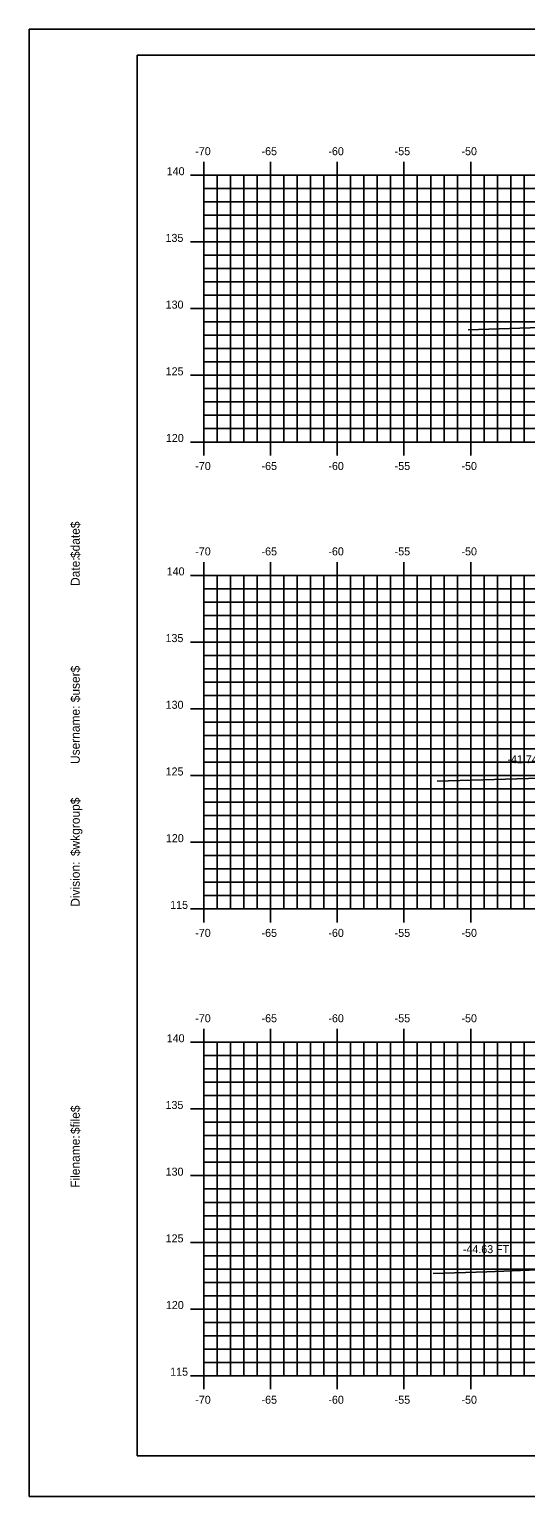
# Model space of a CAD drawing. Extents: x 1146303 to 1146473, y 608981 to 609091.
# Drawn here: x 1146302.8 to 1146340, y 608981.3 to 609091.3 of the extents above; entities that cross this region are included whole.
import ezdxf

# ---------------------------------------------------------------- set-up
doc = ezdxf.new("R2010")
doc.units = 0
for name, color, linetype in [('BORDER', 7, 'Continuous'), ('D_Text_Standard', 7, 'Continuous'), ('H_V ANNOTATION', 7, 'Continuous'), ('MAJOR', 7, 'Continuous'), ('MINOR', 7, 'Continuous'), ('PLOT BOUNDARY', 7, 'Continuous'), ('S_Roadway_Centerline', 7, 'Continuous')]:
    doc.layers.add(name, color=color, linetype=linetype)

msp = doc.modelspace()

# ---------------------------------------------------------------- linework, layer by layer
at = {"layer": 'BORDER'}
msp.add_lwpolyline([(1146310.91, 608984.34), (1146470.91, 608984.34), (1146470.91, 609089.34), (1146310.91, 609089.34)], close=True, dxfattribs=at)
at = {"layer": 'MAJOR'}
for p, q in [((1146315.91, 609081.34), (1146315.91, 609080.34)), ((1146320.91, 609081.34), (1146320.91, 609080.34)), ((1146325.91, 609081.34), (1146325.91, 609080.34)), ((1146330.91, 609081.34), (1146330.91, 609080.34)), ((1146335.91, 609081.34), (1146335.91, 609080.34)), ((1146314.91, 609080.34), (1146315.91, 609080.34)), ((1146315.91, 609080.34), (1146455.91, 609080.34)), ((1146315.91, 609060.34), (1146315.91, 609080.34)), ((1146315.91, 609060.34), (1146315.91, 609080.34)), ((1146315.91, 609080.34), (1146455.91, 609080.34)), ((1146320.91, 609060.34), (1146320.91, 609080.34)), ((1146325.91, 609060.34), (1146325.91, 609080.34)), ((1146330.91, 609060.34), (1146330.91, 609080.34)), ((1146335.91, 609060.34), (1146335.91, 609080.34)), ((1146314.91, 609075.34), (1146315.91, 609075.34)), ((1146315.91, 609075.34), (1146455.91, 609075.34)), ((1146314.91, 609070.34), (1146315.91, 609070.34)), ((1146315.91, 609070.34), (1146455.91, 609070.34)), ((1146314.91, 609065.34), (1146315.91, 609065.34)), ((1146315.91, 609065.34), (1146455.91, 609065.34)), ((1146314.91, 609060.34), (1146315.91, 609060.34)), ((1146315.91, 609060.34), (1146455.91, 609060.34)), ((1146315.91, 609060.34), (1146455.91, 609060.34)), ((1146315.91, 609059.33), (1146315.91, 609060.34)), ((1146320.91, 609059.33), (1146320.91, 609060.34)), ((1146325.91, 609059.33), (1146325.91, 609060.34)), ((1146330.91, 609059.33), (1146330.91, 609060.34)), ((1146335.91, 609059.33), (1146335.91, 609060.34)), ((1146315.91, 609051.34), (1146315.91, 609050.34)), ((1146320.91, 609051.34), (1146320.91, 609050.34)), ((1146325.91, 609051.34), (1146325.91, 609050.34)), ((1146330.91, 609051.34), (1146330.91, 609050.34)), ((1146335.91, 609051.34), (1146335.91, 609050.34)), ((1146314.91, 609050.34), (1146315.91, 609050.34)), ((1146315.91, 609050.34), (1146455.91, 609050.34)), ((1146315.91, 609025.34), (1146315.91, 609050.34)), ((1146315.91, 609025.34), (1146315.91, 609050.34)), ((1146315.91, 609050.34), (1146455.91, 609050.34)), ((1146320.91, 609025.34), (1146320.91, 609050.34)), ((1146325.91, 609025.34), (1146325.91, 609050.34)), ((1146330.91, 609025.34), (1146330.91, 609050.34)), ((1146335.91, 609025.34), (1146335.91, 609050.34)), ((1146314.91, 609045.34), (1146315.91, 609045.34)), ((1146315.91, 609045.34), (1146455.91, 609045.34)), ((1146314.91, 609040.34), (1146315.91, 609040.34)), ((1146315.91, 609040.34), (1146455.91, 609040.34)), ((1146314.91, 609035.34), (1146315.91, 609035.34)), ((1146315.91, 609035.34), (1146455.91, 609035.34)), ((1146314.91, 609030.34), (1146315.91, 609030.34)), ((1146315.91, 609030.34), (1146455.91, 609030.34)), ((1146314.91, 609025.34), (1146315.91, 609025.34)), ((1146315.91, 609025.34), (1146455.91, 609025.34)), ((1146315.91, 609025.34), (1146455.91, 609025.34)), ((1146315.91, 609024.33), (1146315.91, 609025.34)), ((1146320.91, 609024.33), (1146320.91, 609025.34)), ((1146325.91, 609024.33), (1146325.91, 609025.34)), ((1146330.91, 609024.33), (1146330.91, 609025.34)), ((1146335.91, 609024.33), (1146335.91, 609025.34)), ((1146315.91, 609016.34), (1146315.91, 609015.34)), ((1146320.91, 609016.34), (1146320.91, 609015.34)), ((1146325.91, 609016.34), (1146325.91, 609015.34)), ((1146330.91, 609016.34), (1146330.91, 609015.34)), ((1146335.91, 609016.34), (1146335.91, 609015.34)), ((1146314.91, 609015.34), (1146315.91, 609015.34)), ((1146315.91, 609015.34), (1146455.91, 609015.34)), ((1146315.91, 608990.34), (1146315.91, 609015.34)), ((1146315.91, 608990.34), (1146315.91, 609015.34)), ((1146315.91, 609015.34), (1146455.91, 609015.34)), ((1146320.91, 608990.34), (1146320.91, 609015.34)), ((1146325.91, 608990.34), (1146325.91, 609015.34)), ((1146330.91, 608990.34), (1146330.91, 609015.34)), ((1146335.91, 608990.34), (1146335.91, 609015.34)), ((1146314.91, 609010.34), (1146315.91, 609010.34)), ((1146315.91, 609010.34), (1146455.91, 609010.34)), ((1146314.91, 609005.34), (1146315.91, 609005.34)), ((1146315.91, 609005.34), (1146455.91, 609005.34)), ((1146314.91, 609000.34), (1146315.91, 609000.34)), ((1146315.91, 609000.34), (1146455.91, 609000.34)), ((1146314.91, 608995.34), (1146315.91, 608995.34)), ((1146315.91, 608995.34), (1146455.91, 608995.34)), ((1146314.91, 608990.34), (1146315.91, 608990.34)), ((1146315.91, 608990.34), (1146455.91, 608990.34)), ((1146315.91, 608990.34), (1146455.91, 608990.34)), ((1146315.91, 608989.33), (1146315.91, 608990.34)), ((1146320.91, 608989.33), (1146320.91, 608990.34)), ((1146325.91, 608989.33), (1146325.91, 608990.34)), ((1146330.91, 608989.33), (1146330.91, 608990.34)), ((1146335.91, 608989.33), (1146335.91, 608990.34))]:
    msp.add_line(p, q, dxfattribs=at)
at = {"layer": 'MINOR'}
for p, q in [((1146316.91, 609060.34), (1146316.91, 609080.34)), ((1146317.91, 609060.34), (1146317.91, 609080.34)), ((1146318.91, 609060.34), (1146318.91, 609080.34)), ((1146319.91, 609060.34), (1146319.91, 609080.34)), ((1146321.91, 609060.34), (1146321.91, 609080.34)), ((1146322.91, 609060.34), (1146322.91, 609080.34)), ((1146323.91, 609060.34), (1146323.91, 609080.34)), ((1146324.91, 609060.34), (1146324.91, 609080.34)), ((1146326.91, 609060.34), (1146326.91, 609080.34)), ((1146327.91, 609060.34), (1146327.91, 609080.34)), ((1146328.91, 609060.34), (1146328.91, 609080.34)), ((1146329.91, 609060.34), (1146329.91, 609080.34)), ((1146331.91, 609060.34), (1146331.91, 609080.34)), ((1146332.91, 609060.34), (1146332.91, 609080.34)), ((1146333.91, 609060.34), (1146333.91, 609080.34)), ((1146334.91, 609060.34), (1146334.91, 609080.34)), ((1146336.91, 609060.34), (1146336.91, 609080.34)), ((1146337.91, 609060.34), (1146337.91, 609080.34)), ((1146338.91, 609060.34), (1146338.91, 609080.34)), ((1146339.91, 609060.34), (1146339.91, 609080.34)), ((1146315.91, 609079.34), (1146455.91, 609079.34)), ((1146315.91, 609079.34), (1146316.92, 609079.34)), ((1146315.91, 609078.34), (1146455.91, 609078.34)), ((1146315.91, 609078.34), (1146316.92, 609078.34)), ((1146315.91, 609077.34), (1146455.91, 609077.34)), ((1146315.91, 609077.34), (1146316.92, 609077.34)), ((1146315.91, 609076.34), (1146455.91, 609076.34)), ((1146315.91, 609076.34), (1146316.92, 609076.34)), ((1146315.91, 609074.34), (1146455.91, 609074.34)), ((1146315.91, 609074.34), (1146316.92, 609074.34)), ((1146315.91, 609073.34), (1146455.91, 609073.34)), ((1146315.91, 609073.34), (1146316.92, 609073.34)), ((1146315.91, 609072.34), (1146455.91, 609072.34)), ((1146315.91, 609072.34), (1146316.92, 609072.34)), ((1146315.91, 609071.34), (1146455.91, 609071.34)), ((1146315.91, 609071.34), (1146316.92, 609071.34)), ((1146315.91, 609069.34), (1146455.91, 609069.34)), ((1146315.91, 609069.34), (1146316.92, 609069.34)), ((1146315.91, 609068.34), (1146455.91, 609068.34)), ((1146315.91, 609068.34), (1146316.92, 609068.34)), ((1146315.91, 609067.34), (1146455.91, 609067.34)), ((1146315.91, 609067.34), (1146316.92, 609067.34)), ((1146315.91, 609066.34), (1146455.91, 609066.34)), ((1146315.91, 609066.34), (1146316.92, 609066.34)), ((1146315.91, 609064.34), (1146455.91, 609064.34)), ((1146315.91, 609064.34), (1146316.92, 609064.34)), ((1146315.91, 609063.34), (1146455.91, 609063.34)), ((1146315.91, 609063.34), (1146316.92, 609063.34)), ((1146315.91, 609062.34), (1146455.91, 609062.34)), ((1146315.91, 609062.34), (1146316.92, 609062.34)), ((1146315.91, 609061.34), (1146455.91, 609061.34)), ((1146315.91, 609061.34), (1146316.92, 609061.34)), ((1146316.91, 609025.34), (1146316.91, 609050.34)), ((1146317.91, 609025.34), (1146317.91, 609050.34)), ((1146318.91, 609025.34), (1146318.91, 609050.34)), ((1146319.91, 609025.34), (1146319.91, 609050.34)), ((1146321.91, 609025.34), (1146321.91, 609050.34)), ((1146322.91, 609025.34), (1146322.91, 609050.34)), ((1146323.91, 609025.34), (1146323.91, 609050.34)), ((1146324.91, 609025.34), (1146324.91, 609050.34)), ((1146326.91, 609025.34), (1146326.91, 609050.34)), ((1146327.91, 609025.34), (1146327.91, 609050.34)), ((1146328.91, 609025.34), (1146328.91, 609050.34)), ((1146329.91, 609025.34), (1146329.91, 609050.34)), ((1146331.91, 609025.34), (1146331.91, 609050.34)), ((1146332.91, 609025.34), (1146332.91, 609050.34)), ((1146333.91, 609025.34), (1146333.91, 609050.34)), ((1146334.91, 609025.34), (1146334.91, 609050.34)), ((1146336.91, 609025.34), (1146336.91, 609050.34)), ((1146337.91, 609025.34), (1146337.91, 609050.34)), ((1146338.91, 609025.34), (1146338.91, 609050.34)), ((1146339.91, 609025.34), (1146339.91, 609050.34)), ((1146315.91, 609049.34), (1146455.91, 609049.34)), ((1146315.91, 609049.34), (1146316.92, 609049.34)), ((1146315.91, 609048.34), (1146455.91, 609048.34)), ((1146315.91, 609048.34), (1146316.92, 609048.34)), ((1146315.91, 609047.34), (1146455.91, 609047.34)), ((1146315.91, 609047.34), (1146316.92, 609047.34)), ((1146315.91, 609046.34), (1146455.91, 609046.34)), ((1146315.91, 609046.34), (1146316.92, 609046.34)), ((1146315.91, 609044.34), (1146455.91, 609044.34)), ((1146315.91, 609044.34), (1146316.92, 609044.34)), ((1146315.91, 609043.34), (1146455.91, 609043.34)), ((1146315.91, 609043.34), (1146316.92, 609043.34)), ((1146315.91, 609042.34), (1146455.91, 609042.34)), ((1146315.91, 609042.34), (1146316.92, 609042.34)), ((1146315.91, 609041.34), (1146455.91, 609041.34)), ((1146315.91, 609041.34), (1146316.92, 609041.34)), ((1146315.91, 609039.34), (1146455.91, 609039.34)), ((1146315.91, 609039.34), (1146316.92, 609039.34)), ((1146315.91, 609038.34), (1146455.91, 609038.34)), ((1146315.91, 609038.34), (1146316.92, 609038.34)), ((1146315.91, 609037.34), (1146455.91, 609037.34)), ((1146315.91, 609037.34), (1146316.92, 609037.34)), ((1146315.91, 609036.34), (1146455.91, 609036.34)), ((1146315.91, 609036.34), (1146316.92, 609036.34)), ((1146315.91, 609034.34), (1146455.91, 609034.34)), ((1146315.91, 609034.34), (1146316.92, 609034.34)), ((1146315.91, 609033.34), (1146455.91, 609033.34)), ((1146315.91, 609033.34), (1146316.92, 609033.34)), ((1146315.91, 609032.34), (1146455.91, 609032.34)), ((1146315.91, 609032.34), (1146316.92, 609032.34)), ((1146315.91, 609031.34), (1146455.91, 609031.34)), ((1146315.91, 609031.34), (1146316.92, 609031.34)), ((1146315.91, 609029.34), (1146455.91, 609029.34)), ((1146315.91, 609029.34), (1146316.92, 609029.34)), ((1146315.91, 609028.34), (1146455.91, 609028.34)), ((1146315.91, 609028.34), (1146316.92, 609028.34)), ((1146315.91, 609027.34), (1146455.91, 609027.34)), ((1146315.91, 609027.34), (1146316.92, 609027.34)), ((1146315.91, 609026.34), (1146455.91, 609026.34)), ((1146315.91, 609026.34), (1146316.92, 609026.34)), ((1146316.91, 608990.34), (1146316.91, 609015.34)), ((1146317.91, 608990.34), (1146317.91, 609015.34)), ((1146318.91, 608990.34), (1146318.91, 609015.34)), ((1146319.91, 608990.34), (1146319.91, 609015.34)), ((1146321.91, 608990.34), (1146321.91, 609015.34)), ((1146322.91, 608990.34), (1146322.91, 609015.34)), ((1146323.91, 608990.34), (1146323.91, 609015.34)), ((1146324.91, 608990.34), (1146324.91, 609015.34)), ((1146326.91, 608990.34), (1146326.91, 609015.34)), ((1146327.91, 608990.34), (1146327.91, 609015.34)), ((1146328.91, 608990.34), (1146328.91, 609015.34)), ((1146329.91, 608990.34), (1146329.91, 609015.34)), ((1146331.91, 608990.34), (1146331.91, 609015.34)), ((1146332.91, 608990.34), (1146332.91, 609015.34)), ((1146333.91, 608990.34), (1146333.91, 609015.34)), ((1146334.91, 608990.34), (1146334.91, 609015.34)), ((1146336.91, 608990.34), (1146336.91, 609015.34)), ((1146337.91, 608990.34), (1146337.91, 609015.34)), ((1146338.91, 608990.34), (1146338.91, 609015.34)), ((1146339.91, 608990.34), (1146339.91, 609015.34)), ((1146315.91, 609014.34), (1146455.91, 609014.34)), ((1146315.91, 609014.34), (1146316.92, 609014.34)), ((1146315.91, 609013.34), (1146455.91, 609013.34)), ((1146315.91, 609013.34), (1146316.92, 609013.34)), ((1146315.91, 609012.34), (1146455.91, 609012.34)), ((1146315.91, 609012.34), (1146316.92, 609012.34)), ((1146315.91, 609011.34), (1146455.91, 609011.34)), ((1146315.91, 609011.34), (1146316.92, 609011.34)), ((1146315.91, 609009.34), (1146455.91, 609009.34)), ((1146315.91, 609009.34), (1146316.92, 609009.34)), ((1146315.91, 609008.34), (1146455.91, 609008.34)), ((1146315.91, 609008.34), (1146316.92, 609008.34)), ((1146315.91, 609007.34), (1146455.91, 609007.34)), ((1146315.91, 609007.34), (1146316.92, 609007.34)), ((1146315.91, 609006.34), (1146455.91, 609006.34)), ((1146315.91, 609006.34), (1146316.92, 609006.34)), ((1146315.91, 609004.34), (1146455.91, 609004.34)), ((1146315.91, 609004.34), (1146316.92, 609004.34)), ((1146315.91, 609003.34), (1146455.91, 609003.34)), ((1146315.91, 609003.34), (1146316.92, 609003.34)), ((1146315.91, 609002.34), (1146455.91, 609002.34)), ((1146315.91, 609002.34), (1146316.92, 609002.34)), ((1146315.91, 609001.34), (1146455.91, 609001.34)), ((1146315.91, 609001.34), (1146316.92, 609001.34)), ((1146315.91, 608999.34), (1146455.91, 608999.34)), ((1146315.91, 608999.34), (1146316.92, 608999.34)), ((1146315.91, 608998.34), (1146455.91, 608998.34)), ((1146315.91, 608998.34), (1146316.92, 608998.34)), ((1146315.91, 608997.34), (1146455.91, 608997.34)), ((1146315.91, 608997.34), (1146316.92, 608997.34)), ((1146315.91, 608996.34), (1146455.91, 608996.34)), ((1146315.91, 608996.34), (1146316.92, 608996.34)), ((1146315.91, 608994.34), (1146455.91, 608994.34)), ((1146315.91, 608994.34), (1146316.92, 608994.34)), ((1146315.91, 608993.34), (1146455.91, 608993.34)), ((1146315.91, 608993.34), (1146316.92, 608993.34)), ((1146315.91, 608992.34), (1146455.91, 608992.34)), ((1146315.91, 608992.34), (1146316.92, 608992.34)), ((1146315.91, 608991.34), (1146455.91, 608991.34)), ((1146315.91, 608991.34), (1146316.92, 608991.34))]:
    msp.add_line(p, q, dxfattribs=at)
at = {"layer": 'PLOT BOUNDARY'}
msp.add_lwpolyline([(1146302.82, 608981.28), (1146472.82, 608981.28), (1146472.82, 609091.28), (1146302.82, 609091.28)], close=True, dxfattribs=at)
at = {"layer": 'S_Roadway_Centerline'}
for points in [[(1146335.72, 609068.74), (1146341.91, 609068.95), (1146350.5, 609068.65), (1146356.17, 609069.12), (1146361.35, 609069.45), (1146366.35, 609070.04), (1146369.93, 609070.73), (1146371.98, 609070.83), (1146373.05, 609070.9), (1146381.58, 609071.16), (1146383.91, 609071.22), (1146392.61, 609070.96), (1146394.83, 609070.89), (1146395.63, 609070.83), (1146398.84, 609070.42), (1146399.62, 609070.06), (1146402.46, 609069.28), (1146409.53, 609069.26), (1146410.11, 609069.37), (1146413.56, 609069.37), (1146429.26, 609069.82), (1146435.48, 609069.99)], [(1146333.39, 609034.91), (1146346.21, 609035.29), (1146349.13, 609035.41), (1146357.59, 609036.33), (1146359.82, 609036.53), (1146361.27, 609036.81), (1146369.1, 609038.22), (1146370.96, 609038.37), (1146372.74, 609038.61), (1146374.65, 609038.67), (1146383.69, 609038.94), (1146385.69, 609038.86), (1146395.03, 609038.54), (1146397.89, 609038.18), (1146398.57, 609038.1), (1146401.63, 609036.96), (1146404.95, 609035.24), (1146408.84, 609036.39), (1146410.17, 609037.51), (1146433.85, 609040.48), (1146437.53, 609040.85)], [(1146333.1, 608998), (1146337.13, 608998.12), (1146349.15, 608998.6), (1146351.61, 608998.85), (1146359.48, 608999.63), (1146363.26, 609000.63), (1146368.63, 609001.83), (1146370.3, 609001.99), (1146372.45, 609002.23), (1146378.33, 609002.42), (1146383.8, 609002.59), (1146389.23, 609002.43), (1146394.81, 609002.21), (1146396.68, 609001.98), (1146398.46, 609001.77), (1146403.06, 608998.9), (1146403.62, 608998.57), (1146408.5, 609000.65), (1146410.68, 609001.55), (1146412.04, 609001.76), (1146432.73, 609005.07)]]:
    msp.add_lwpolyline(points, dxfattribs=at)

# ---------------------------------------------------------------- texts
at = {"layer": 'BORDER'}
for s, p in [('$date$', (1146306.6, 609051.64)), ('Date:', (1146306.6, 609049.55)), ('$user$', (1146306.6, 609040.83)), ('Username:', (1146306.6, 609036.2)), ('$wkgroup$', (1146306.6, 609029.3)), ('Division:', (1146306.6, 609025.5)), ('$file$', (1146306.6, 609008.46)), ('Filename:', (1146306.6, 609004.43))]:
    msp.add_text(s, height=0.67, rotation=90, dxfattribs=at).set_placement(p)
at = {"layer": 'D_Text_Standard'}
for s, p in [('-41.74 FT', (1146338.66, 609036.25)), ('-44.63 FT', (1146335.32, 608999.53))]:
    msp.add_text(s, height=0.6, dxfattribs=at).set_placement(p)
at = {"layer": 'H_V ANNOTATION'}
for s, p in [('-70', (1146315.26, 609081.84)), ('-65', (1146320.23, 609081.84)), ('-60', (1146325.24, 609081.84)), ('-55', (1146330.21, 609081.84)), ('-50', (1146335.22, 609081.84)), ('140', (1146313.12, 609080.34)), ('135', (1146313.03, 609075.34)), ('130', (1146313.04, 609070.34)), ('125', (1146313.04, 609065.34)), ('120', (1146313.06, 609060.34)), ('-70', (1146315.26, 609058.24)), ('-65', (1146320.23, 609058.24)), ('-60', (1146325.24, 609058.24)), ('-55', (1146330.21, 609058.24)), ('-50', (1146335.22, 609058.24)), ('-70', (1146315.26, 609051.84)), ('-65', (1146320.23, 609051.84)), ('-60', (1146325.24, 609051.84)), ('-55', (1146330.21, 609051.84)), ('-50', (1146335.22, 609051.84)), ('140', (1146313.12, 609050.34)), ('135', (1146313.03, 609045.34)), ('130', (1146313.04, 609040.34)), ('125', (1146313.04, 609035.34)), ('120', (1146313.06, 609030.34)), ('115', (1146313.38, 609025.34)), ('-70', (1146315.26, 609023.24)), ('-65', (1146320.23, 609023.24)), ('-60', (1146325.24, 609023.24)), ('-55', (1146330.21, 609023.24)), ('-50', (1146335.22, 609023.24)), ('-70', (1146315.26, 609016.84)), ('-65', (1146320.23, 609016.84)), ('-60', (1146325.24, 609016.84)), ('-55', (1146330.21, 609016.84)), ('-50', (1146335.22, 609016.84)), ('140', (1146313.12, 609015.34)), ('135', (1146313.03, 609010.34)), ('130', (1146313.04, 609005.34)), ('125', (1146313.04, 609000.34)), ('120', (1146313.06, 608995.34)), ('115', (1146313.38, 608990.34)), ('-70', (1146315.26, 608988.24)), ('-65', (1146320.23, 608988.24)), ('-60', (1146325.24, 608988.24)), ('-55', (1146330.21, 608988.24)), ('-50', (1146335.22, 608988.24))]:
    msp.add_text(s, height=0.6, dxfattribs=at).set_placement(p)
at = {"layer": 'MAJOR'}
for p in [(1146315.91, 609060.34), (1146315.91, 609025.34), (1146315.91, 608990.34)]:
    msp.add_text('-', height=0.006, dxfattribs=at).set_placement(p)

doc.saveas('drawing.dxf')
